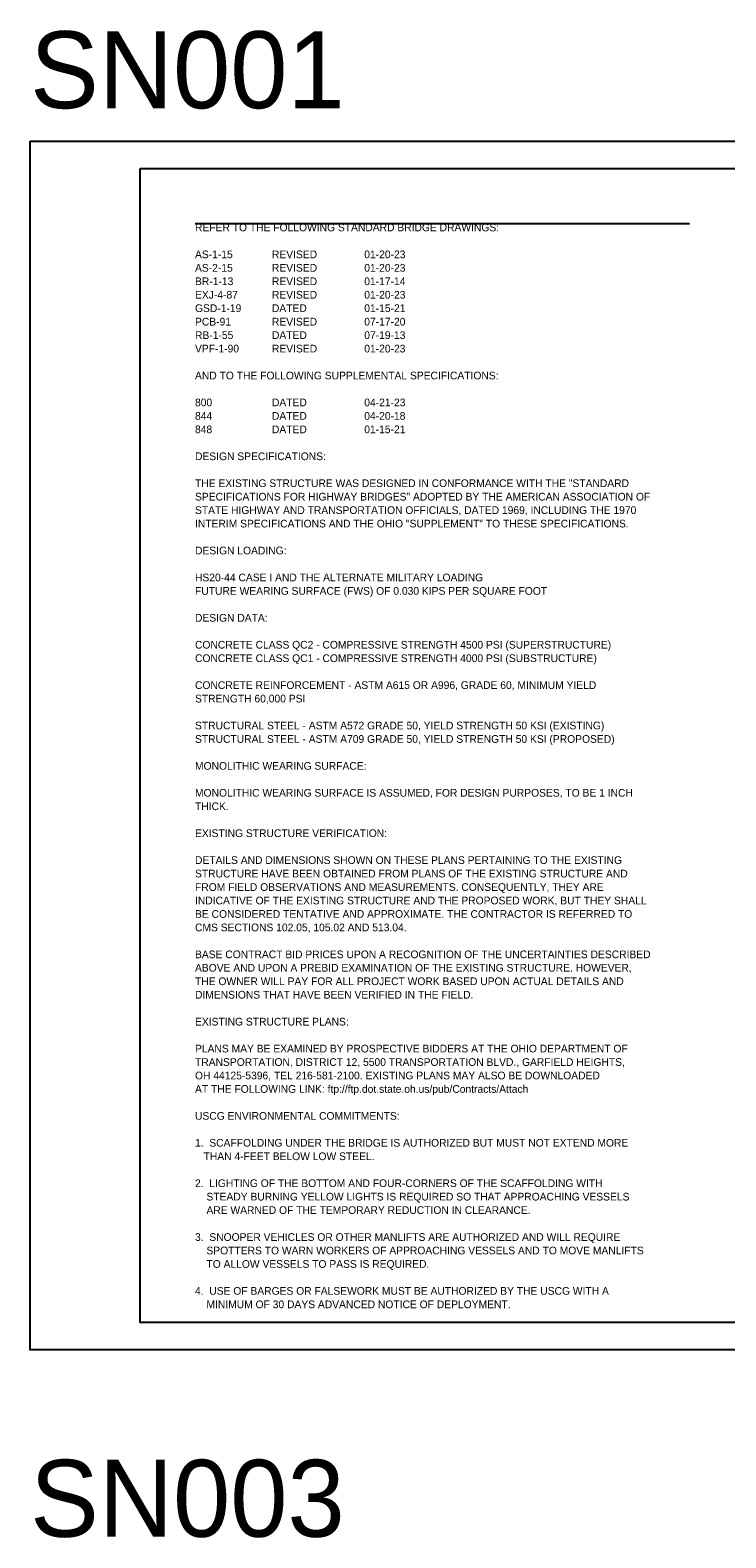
# Model space of a CAD drawing. Extents: x 0 to 72, y -26 to 50.
# Drawn here: x 0 to 12.66, y 22.58 to 50.02 of the extents above; entities that cross this region are included whole.
import ezdxf

# ---------------------------------------------------------------- set-up
doc = ezdxf.new("R2010")
doc.units = 0
doc.layers.add('SH_Cut_Line', color=7, linetype='Continuous')
doc.layers.add('SH_Data', color=7, linetype='Continuous')

msp = doc.modelspace()

# ---------------------------------------------------------------- linework, layer by layer
at = {"layer": 'SH_Cut_Line'}
msp.add_line((3, 46.5), (12, 46.5), dxfattribs=at)
for points in [[(0, 48), (34, 48), (34, 26), (0, 26)], [(2, 47.5), (32.5, 47.5), (32.5, 26.5), (2, 26.5)]]:
    msp.add_lwpolyline(points, close=True, dxfattribs=at)

# ---------------------------------------------------------------- texts
at = {"layer": 'SH_Data'}
for s, height, p in [('SN001', 1.4, (0, 48.6)), ('REFER TO THE FOLLOWING STANDARD BRIDGE DRAWINGS:', 0.14, (3, 46.36)), ('REFER TO THE FOLLOWING STANDARD BRIDGE DRAWINGS:', 0.14, (3, 46.36)), ('AS-1-15', 0.14, (3, 45.87)), ('REVISED', 0.14, (4.4, 45.87)), ('01-20-23', 0.14, (6.08, 45.87)), ('AS-2-15', 0.14, (3, 45.625)), ('REVISED', 0.14, (4.4, 45.625)), ('01-20-23', 0.14, (6.08, 45.625)), ('BR-1-13', 0.14, (3, 45.38)), ('REVISED', 0.14, (4.4, 45.38)), ('01-17-14', 0.14, (6.08, 45.38)), ('GSD-1-19', 0.14, (3, 44.89)), ('EXJ-4-87', 0.14, (3, 45.135)), ('REVISED', 0.14, (4.4, 45.135)), ('DATED', 0.14, (4.4, 44.89)), ('01-20-23', 0.14, (6.08, 45.135)), ('01-15-21', 0.14, (6.08, 44.89)), ('PCB-91', 0.14, (3, 44.645)), ('REVISED', 0.14, (4.4, 44.645)), ('07-17-20', 0.14, (6.08, 44.645)), ('RB-1-55', 0.14, (3, 44.4)), ('DATED', 0.14, (4.4, 44.4)), ('07-19-13', 0.14, (6.08, 44.4)), ('VPF-1-90', 0.14, (3, 44.155)), ('REVISED', 0.14, (4.4, 44.155)), ('01-20-23', 0.14, (6.08, 44.155)), ('AND TO THE FOLLOWING SUPPLEMENTAL SPECIFICATIONS:', 0.14, (3, 43.665)), ('AND TO THE FOLLOWING SUPPLEMENTAL SPECIFICATIONS:', 0.14, (3, 43.665)), ('800', 0.14, (3, 43.175)), ('DATED', 0.14, (4.4, 43.175)), ('04-21-23', 0.14, (6.08, 43.175)), ('844', 0.14, (3, 42.93)), ('848', 0.14, (3, 42.685)), ('DATED', 0.14, (4.4, 42.93)), ('DATED', 0.14, (4.4, 42.685)), ('04-20-18', 0.14, (6.08, 42.93)), ('01-15-21', 0.14, (6.08, 42.685)), ('DESIGN SPECIFICATIONS:', 0.14, (3, 42.195)), ('DESIGN SPECIFICATIONS:', 0.14, (3, 42.195)), ('THE EXISTING STRUCTURE WAS DESIGNED IN CONFORMANCE WITH THE "STANDARD ', 0.14, (3, 41.705)), ('SPECIFICATIONS FOR HIGHWAY BRIDGES" ADOPTED BY THE AMERICAN ASSOCIATION OF ', 0.14, (3, 41.46)), ('STATE HIGHWAY AND TRANSPORTATION OFFICIALS, DATED 1969, INCLUDING THE 1970 ', 0.14, (3, 41.215)), ('INTERIM SPECIFICATIONS AND THE OHIO "SUPPLEMENT" TO THESE SPECIFICATIONS.', 0.14, (3, 40.97)), ('DESIGN LOADING:', 0.14, (3, 40.48)), ('DESIGN LOADING:', 0.14, (3, 40.48)), ('HS20-44 CASE I AND THE ALTERNATE MILITARY LOADING', 0.14, (3, 39.99)), ('FUTURE WEARING SURFACE (FWS) OF 0.030 KIPS PER SQUARE FOOT', 0.14, (3, 39.745)), ('DESIGN DATA:', 0.14, (3, 39.255)), ('DESIGN DATA:', 0.14, (3, 39.255)), ('CONCRETE CLASS QC2 - COMPRESSIVE STRENGTH 4500 PSI (SUPERSTRUCTURE)', 0.14, (3, 38.765)), ('CONCRETE CLASS QC1 - COMPRESSIVE STRENGTH 4000 PSI (SUBSTRUCTURE)', 0.14, (3, 38.52)), ('CONCRETE REINFORCEMENT - ASTM A615 OR A996, GRADE 60, MINIMUM YIELD               ', 0.14, (3, 38.03)), ('STRENGTH 60,000 PSI', 0.14, (3, 37.785)), ('STRUCTURAL STEEL - ASTM A572 GRADE 50, YIELD STRENGTH 50 KSI (EXISTING)', 0.14, (3, 37.295)), ('STRUCTURAL STEEL - ASTM A709 GRADE 50, YIELD STRENGTH 50 KSI (PROPOSED)', 0.14, (3, 37.05)), ('MONOLITHIC WEARING SURFACE:', 0.14, (3, 36.56)), ('MONOLITHIC WEARING SURFACE:', 0.14, (3, 36.56)), ('THICK.', 0.14, (3, 35.825)), ('MONOLITHIC WEARING SURFACE IS ASSUMED, FOR DESIGN PURPOSES, TO BE 1 INCH ', 0.14, (3, 36.07)), ('EXISTING STRUCTURE VERIFICATION:', 0.14, (3, 35.335)), ('EXISTING STRUCTURE VERIFICATION:', 0.14, (3, 35.335)), ('DETAILS AND DIMENSIONS SHOWN ON THESE PLANS PERTAINING TO THE EXISTING ', 0.14, (3, 34.845)), ('STRUCTURE HAVE BEEN OBTAINED FROM PLANS OF THE EXISTING STRUCTURE AND ', 0.14, (3, 34.6)), ('FROM FIELD OBSERVATIONS AND MEASUREMENTS. CONSEQUENTLY, THEY ARE ', 0.14, (3, 34.355)), ('INDICATIVE OF THE EXISTING STRUCTURE AND THE PROPOSED WORK, BUT THEY SHALL ', 0.14, (3, 34.11)), ('CMS SECTIONS 102.05, 105.02 AND 513.04.', 0.14, (3, 33.62)), ('BE CONSIDERED TENTATIVE AND APPROXIMATE. THE CONTRACTOR IS REFERRED TO ', 0.14, (3, 33.865)), ('BASE CONTRACT BID PRICES UPON A RECOGNITION OF THE UNCERTAINTIES DESCRIBED ', 0.14, (3, 33.13)), ('ABOVE AND UPON A PREBID EXAMINATION OF THE EXISTING STRUCTURE. HOWEVER, ', 0.14, (3, 32.885)), ('THE OWNER WILL PAY FOR ALL PROJECT WORK BASED UPON ACTUAL DETAILS AND ', 0.14, (3, 32.64)), ('DIMENSIONS THAT HAVE BEEN VERIFIED IN THE FIELD.', 0.14, (3, 32.395)), ('EXISTING STRUCTURE PLANS:', 0.14, (3, 31.905)), ('EXISTING STRUCTURE PLANS:', 0.14, (3, 31.905)), ('PLANS MAY BE EXAMINED BY PROSPECTIVE BIDDERS AT THE OHIO DEPARTMENT OF ', 0.14, (3, 31.415)), ('TRANSPORTATION, DISTRICT 12, 5500 TRANSPORTATION BLVD., GARFIELD HEIGHTS, ', 0.14, (3, 31.17)), ('OH 44125-5396, TEL 216-581-2100. EXISTING PLANS MAY ALSO BE DOWNLOADED', 0.14, (3, 30.925)), ('AT THE FOLLOWING LINK: ftp://ftp.dot.state.oh.us/pub/Contracts/Attach', 0.14, (3, 30.68)), ('USCG ENVIRONMENTAL COMMITMENTS: ', 0.14, (3, 30.19)), ('USCG ENVIRONMENTAL COMMITMENTS: ', 0.14, (3, 30.19)), ('1.  SCAFFOLDING UNDER THE BRIDGE IS AUTHORIZED BUT MUST NOT EXTEND MORE ', 0.14, (3, 29.7)), ('   THAN 4-FEET BELOW LOW STEEL.', 0.14, (3, 29.455)), ('2.  LIGHTING OF THE BOTTOM AND FOUR-CORNERS OF THE SCAFFOLDING WITH ', 0.14, (3, 28.965)), ('    STEADY BURNING YELLOW LIGHTS IS REQUIRED SO THAT APPROACHING VESSELS ', 0.14, (3, 28.72)), ('    ARE WARNED OF THE TEMPORARY REDUCTION IN CLEARANCE. ', 0.14, (3, 28.475)), ('3.  SNOOPER VEHICLES OR OTHER MANLIFTS ARE AUTHORIZED AND WILL REQUIRE  ', 0.14, (3, 27.985)), ('    SPOTTERS TO WARN WORKERS OF APPROACHING VESSELS AND TO MOVE MANLIFTS ', 0.14, (3, 27.74)), ('    TO ALLOW VESSELS TO PASS IS REQUIRED.', 0.14, (3, 27.495)), ('4.  USE OF BARGES OR FALSEWORK MUST BE AUTHORIZED BY THE USCG WITH A ', 0.14, (3, 27.005)), ('    MINIMUM OF 30 DAYS ADVANCED NOTICE OF DEPLOYMENT.', 0.14, (3, 26.76)), ('SN003', 1.4, (0, 22.6))]:
    msp.add_text(s, height=height, dxfattribs=at).set_placement(p)

doc.saveas('drawing.dxf')
